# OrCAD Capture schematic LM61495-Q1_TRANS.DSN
size D; title: LM61495-Q1: 6A/8A/10-A Automotive Buck Converter; rev: 1.0; note: Datasheet: SNVSBQ1     EVM: NA; note: Synchronous Step Down Converter
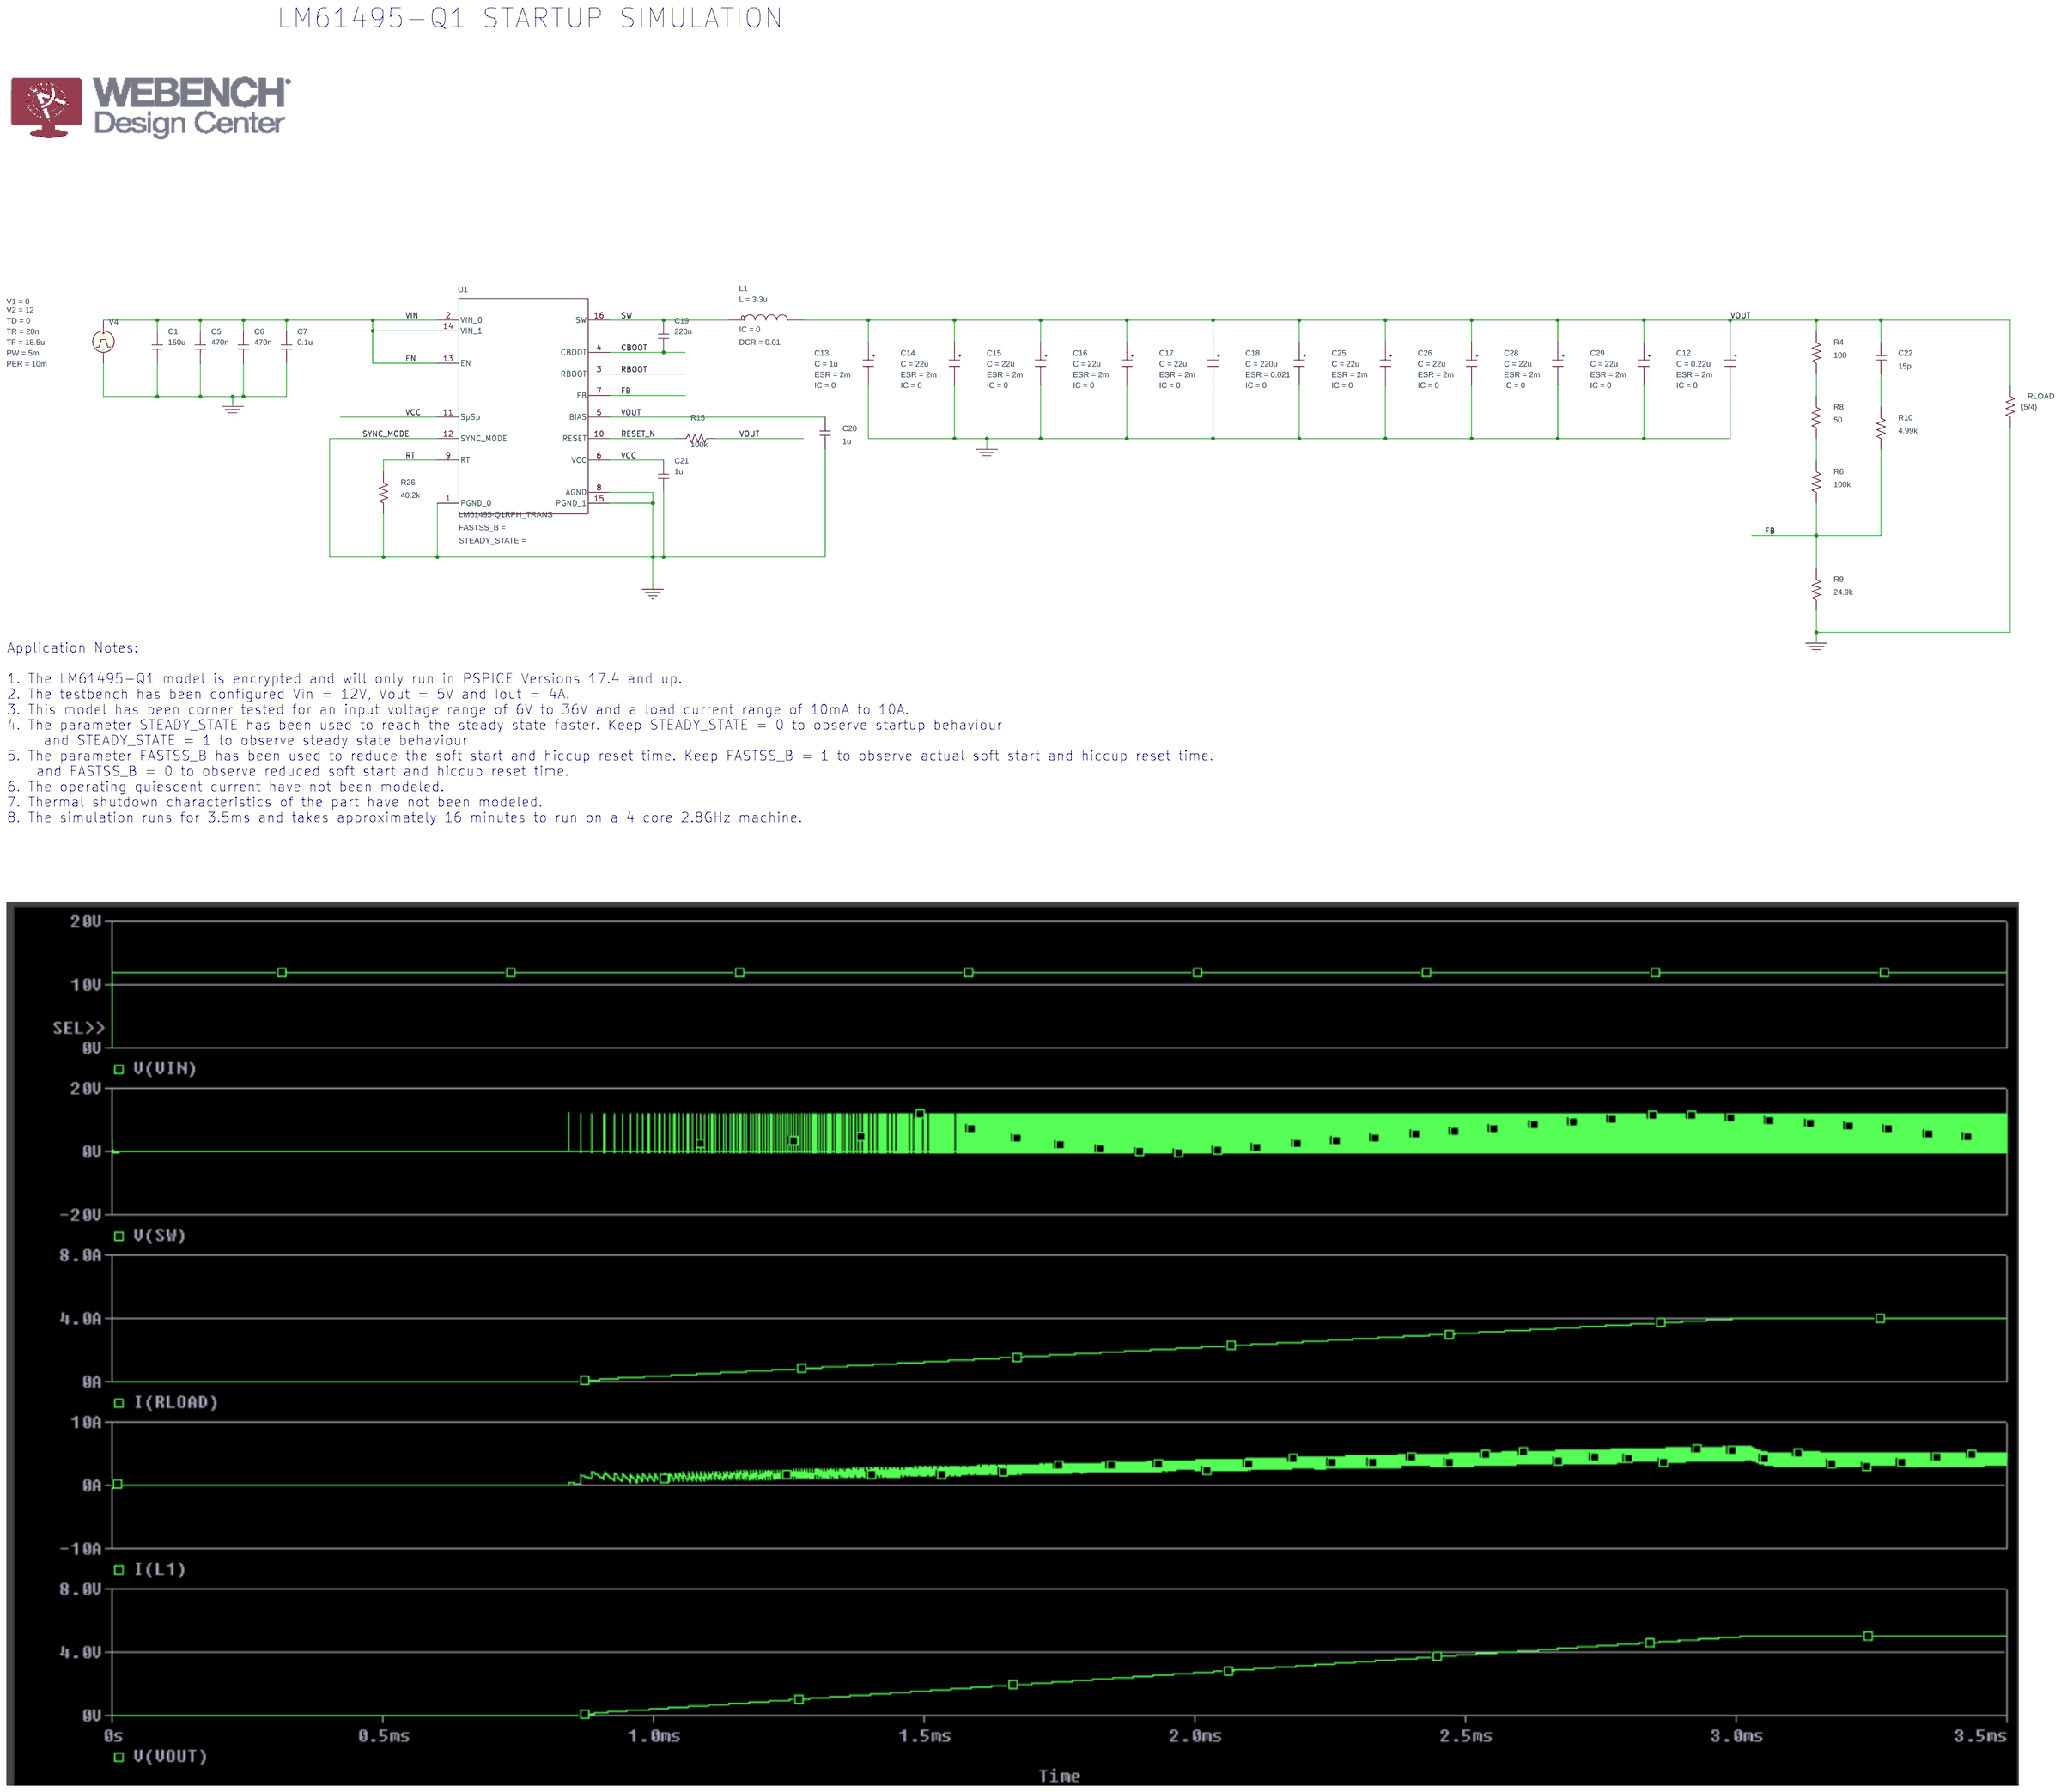
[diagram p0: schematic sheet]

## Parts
C1  150u  [RAD/CK05]
C5  470n  [RAD/CK05]
C6  470n  [RAD/CK05]
C7  0.1u  [RAD/CK05]
C12  CESR
C13  CESR
C14  CESR
C15  CESR
C16  CESR
C17  CESR
C18  CESR
C19  220n  [RAD/CK05]
C20  1u  [RAD/CK05]
C21  1u  [RAD/CK05]
C22  15p  [RAD/CK05]
C25  CESR
C26  CESR
C28  CESR
C29  CESR
L1  LDCR
R4  100  [AX/RC05]
R6  100k  [AX/RC05]
R8  50  [AX/RC05]
R9  24.9k  [AX/RC05]
R10  4.99k  [AX/RC05]
R15  100k  [AX/RC05]
R26  40.2k  [AX/RC05]
RLOAD  {5/4}  [AX/RC05]
U1  LM61495-Q1RPH_TRANS  [RPH0016A]
V4  VPULSE

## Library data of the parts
C1 C5-C7 C19-C22 = C
C12 = CESR_0: C: 0.22u; ESR: 2m; IC: 0; PSpiceTemplate: X^@REFDES %IN %OUT @MODEL PARAMS:  ?C|C=@C||C=100u|  ?ESR|ESR=@ESR||ESR=0.01| ?X|X=@X||X=2|  ?IC|IC=@IC||IC=2|; X: 1
C13 = CESR_0: C: 1u; ESR: 2m; IC: 0; PSpiceTemplate: X^@REFDES %IN %OUT @MODEL PARAMS:  ?C|C=@C||C=100u|  ?ESR|ESR=@ESR||ESR=0.01| ?X|X=@X||X=2|  ?IC|IC=@IC||IC=2|; X: 1
C14-C17 C25 C26 C28 C29 = CESR_0: C: 22u; ESR: 2m; IC: 0; PSpiceTemplate: X^@REFDES %IN %OUT @MODEL PARAMS:  ?C|C=@C||C=100u|  ?ESR|ESR=@ESR||ESR=0.01| ?X|X=@X||X=2|  ?IC|IC=@IC||IC=2|; X: 1
C18 = CESR_0: C: 220u; ESR: 0.021; IC: 0; PSpiceTemplate: X^@REFDES %IN %OUT @MODEL PARAMS:  ?C|C=@C||C=100u|  ?ESR|ESR=@ESR||ESR=0.01| ?X|X=@X||X=2|  ?IC|IC=@IC||IC=2|; X: 1
L1 = LDCR_0: DCR: 0.01; IC: 0; L: 3.3u; PSpiceTemplate: X^@REFDES %IN %OUT @MODEL PARAMS:  ?L|L=@L||L=1u|  ?DCR|DCR=@DCR||DCR=0.01| ?IC|IC=@IC||IC=0|
R4 R6 R8-R10 R15 R26 RLOAD = r
U1 = LM61495-Q1RPH_TRANS
V4 = VPULSE: PER: 10m; PW: 5m; TD: 0; TF: 18.5u; TR: 20n; V1: 0; V2: 12

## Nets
VCC: C21.1 U1.6(VCC) U1.11(SpSp)
0: C1.2 C5.2 C6.2 C7.2 C12.2(OUT) C13.2(OUT) C14.2(OUT) C15.2(OUT) C16.2(OUT) C17.2(OUT) C18.2(OUT) C20.2 C21.2 C25.2(OUT) C26.2(OUT) C28.2(OUT) C29.2(OUT) R9.2 R26.2 RLOAD.2 U1.1(PGND_0) U1.8(AGND) U1.12(SYNC_MODE) U1.15(PGND_1) V4.2(-)
CBOOT: C19.2 U1.4(CBOOT)
EN: C1.1 C5.1 C6.1 C7.1 U1.2(VIN_0) U1.13(EN) U1.14(VIN_1) V4.1(+)
FB: R6.2 R9.1 R10.2 U1.7(FB)
RBOOT: U1.3(RBOOT)
RESET_N: R15.1 U1.10(RESET)
RT: R26.1 U1.9(RT)
SW: C19.1 L1.1(IN) U1.16(SW)
VOUT: C12.1(IN) C13.1(IN) C14.1(IN) C15.1(IN) C16.1(IN) C17.1(IN) C18.1(IN) C20.1 C22.1 C25.1(IN) C26.1(IN) C28.1(IN) C29.1(IN) L1.3(OUT) R4.1 R15.2 RLOAD.1 U1.5(BIAS)
N16770438: C22.2 R10.1
N16772417: R4.2 R8.1
N16772470: R6.1 R8.2

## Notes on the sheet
- LM61495-Q1 STARTUP SIMULATION
- Application Notes:
  1. The LM61495-Q1 model is encrypted and will only run in PSPICE Versions 17.4 and up.
  2. The testbench has been configured Vin = 12V, Vout = 5V and Iout = 4A.
  3. This model has been corner tested for an input voltage range of 6V to 36V and a load current range of 10mA to 10A.
  4. The parameter STEADY_STATE has been used to reach the steady state faster. Keep STEADY_STATE = 0 to observe startup behaviour
       and STEADY_STATE = 1 to observe steady state behaviour
  5. The parameter FASTSS_B has been used to reduce the soft start and hiccup reset time. Keep FASTSS_B = 1 to observe actual soft start and hiccup reset time.
      and FASTSS_B = 0 to observe reduced soft start and hiccup reset time.
  6. The operating quiescent current have not been modeled.
  7. Thermal shutdown characteristics of the part have not been modeled.
  8. The simulation runs for 3.5ms and takes approximately 16 minutes to run on a 4 core 2.8GHz machine.
